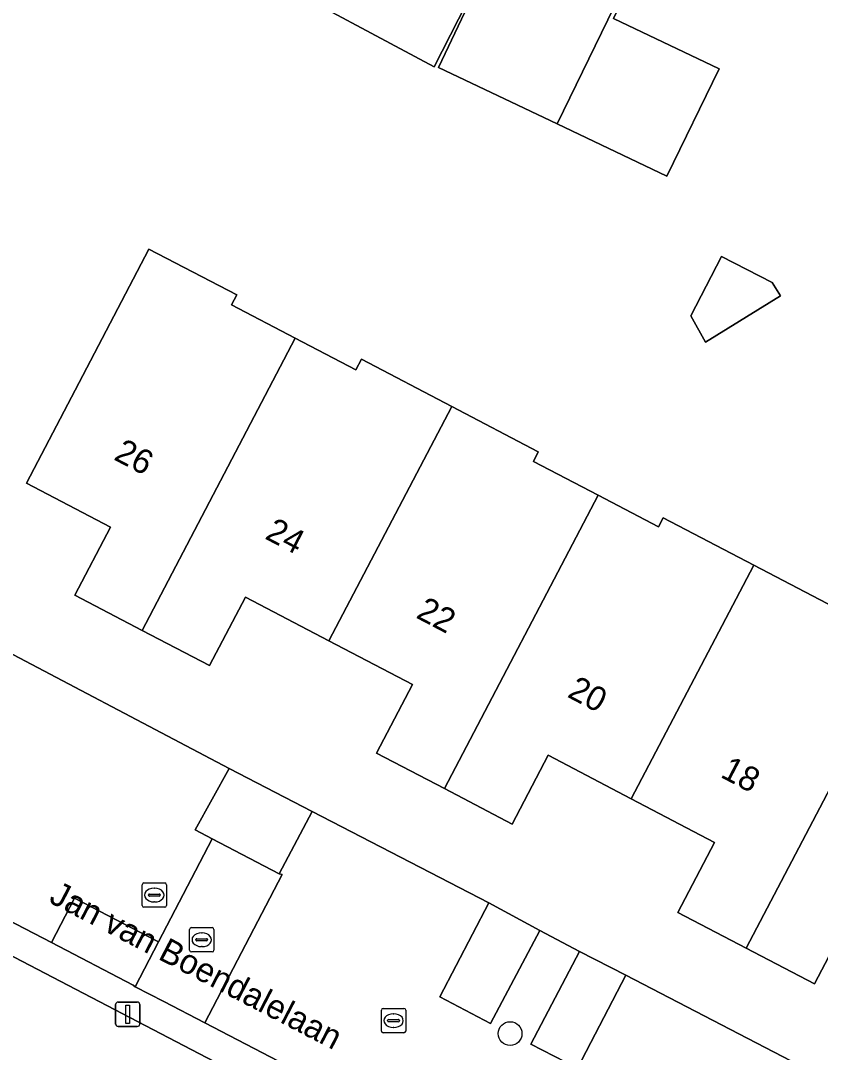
# Model space of a CAD drawing. Extents: x 160349 to 161355, y 381727 to 382854.
# Drawn here: x 160733.31 to 160766.17, y 382411.9 to 382454.27 of the extents above; entities that cross this region are included whole.
import ezdxf

# ---------------------------------------------------------------- set-up
doc = ezdxf.new("R2010")
doc.units = 0
for name, color, linetype in [('IMGEO_Boom', 7, 'Continuous'), ('IMGEO_Erf', 7, 'Continuous'), ('IMGEO_Groenvoorziening', 7, 'Continuous'), ('IMGEO_Kolk', 7, 'Continuous'), ('IMGEO_Lichtmast', 7, 'Continuous'), ('IMGEO_Openbare_ruimte_label', 7, 'Continuous'), ('IMGEO_Pand', 7, 'Continuous'), ('IMGEO_Pand_nummerreeks', 7, 'Continuous'), ('IMGEO_Parkeervlak_open', 7, 'Continuous'), ('IMGEO_Rioolput', 7, 'Continuous'), ('IMGEO_Voetpad_open', 7, 'Continuous'), ('IMGEO_Woonerf_open', 7, 'Continuous')]:
    doc.layers.add(name, color=color, linetype=linetype)

msp = doc.modelspace()

# ---------------------------------------------------------------- linework, layer by layer
at = {"layer": 'IMGEO_Boom'}
msp.add_circle((160753.42, 382412.667), 0.489, dxfattribs=at)
at = {"layer": 'IMGEO_Erf'}
for points in [[(160753.641, 382458.935), (160750.295, 382452.378), (160743.332, 382456.11)], [(160767.405, 382417.538), (160765.925, 382414.706), (160763.12, 382416.172), (160760.315, 382417.638), (160761.822, 382420.523), (160758.4, 382422.312), (160754.98, 382424.099), (160753.503, 382421.274), (160750.719, 382422.729), (160747.937, 382424.183), (160749.414, 382427.009), (160745.979, 382428.804), (160742.547, 382430.598), (160741.075, 382427.781), (160738.305, 382429.229), (160735.537, 382430.675), (160736.999, 382433.471), (160733.557, 382435.27), (160735.873, 382439.702), (160738.583, 382444.889), (160742.192, 382443.003), (160741.976, 382442.591), (160744.597, 382441.222), (160747.082, 382439.923), (160747.311, 382440.361), (160751.024, 382438.42), (160754.58, 382436.561), (160754.376, 382436.17), (160757.04, 382434.777), (160759.514, 382433.484), (160759.706, 382433.851), (160763.432, 382431.904), (160767.042, 382430.017)], [(160698.651, 382444.432), (160706.474, 382440.908), (160712.236, 382438.345), (160715.645, 382436.842), (160717.302, 382436.075), (160719.442, 382435.153), (160727.083, 382431.251), (160727.158, 382431.213), (160731.438, 382429.052), (160731.474, 382429.033), (160741.875, 382423.552), (160745.289, 382421.796), (160752.547, 382418.032), (160754.638, 382416.907), (160756.272, 382416.046), (160758.175, 382415.068), (160765.328, 382411.355)], [(160782.234, 382390.225), (160773.298, 382394.819), (160708.642, 382428.527)]]:
    msp.add_lwpolyline(points, dxfattribs=at)
for points in [[(160750.475, 382452.351), (160753.04, 382457.734), (160757.962, 382455.388), (160758.122, 382455.312), (160757.669, 382454.362), (160762.014, 382452.291), (160759.861, 382447.879), (160755.348, 382450.029)], [(160762.111, 382444.577), (160764.189, 382443.508), (160764.527, 382442.962), (160761.449, 382441.065), (160760.839, 382442.143)]]:
    msp.add_lwpolyline(points, close=True, dxfattribs=at)
at = {"layer": 'IMGEO_Groenvoorziening'}
msp.add_lwpolyline([(160743.928, 382419.236), (160745.289, 382421.796), (160741.875, 382423.552), (160740.483, 382421.031), (160741.176, 382420.67)], close=True, dxfattribs=at)
at = {"layer": 'IMGEO_Kolk'}
for p, q in [((160738.305, 382417.93), (160738.305, 382418.782)), ((160738.38, 382418.856), (160739.232, 382418.856)), ((160738.793, 382418.636), (160738.818, 382418.636)), ((160739.306, 382418.782), (160739.306, 382417.93)), ((160738.564, 382418.35), (160738.564, 382418.362)), ((160739.002, 382418.313), (160738.604, 382418.313)), ((160738.607, 382418.399), (160739.005, 382418.399)), ((160739.048, 382418.362), (160739.048, 382418.35)), ((160739.232, 382417.856), (160738.38, 382417.856)), ((160738.816, 382418.076), (160738.791, 382418.076)), ((160748.131, 382412.775), (160748.131, 382413.627)), ((160748.206, 382413.701), (160749.058, 382413.701)), ((160748.619, 382413.481), (160748.644, 382413.481)), ((160749.132, 382413.627), (160749.132, 382412.775)), ((160748.39, 382413.195), (160748.39, 382413.207)), ((160748.828, 382413.158), (160748.43, 382413.158)), ((160748.433, 382413.244), (160748.831, 382413.244)), ((160748.874, 382413.207), (160748.874, 382413.195)), ((160749.058, 382412.701), (160748.206, 382412.701)), ((160748.642, 382412.921), (160748.617, 382412.921))]:
    msp.add_line(p, q, dxfattribs=at)
for points in [[(160738.305, 382417.93), (160738.305, 382418.782)], [(160738.38, 382418.856), (160739.232, 382418.856)], [(160739.306, 382418.782), (160739.306, 382417.93)], [(160739.232, 382417.856), (160738.38, 382417.856)], [(160748.131, 382412.775), (160748.131, 382413.627)], [(160748.206, 382413.701), (160749.058, 382413.701)], [(160749.132, 382413.627), (160749.132, 382412.775)], [(160749.058, 382412.701), (160748.206, 382412.701)]]:
    msp.add_lwpolyline(points, dxfattribs=at)
for centre, radius, start, end in [((160738.382, 382418.78), 0.0765, 91.552, 178.448), ((160738.382, 382418.78), 0.0765, 91.552, 178.448), ((160739.23, 382418.78), 0.0765, 1.552, 88.448), ((160739.23, 382418.78), 0.0765, 1.552, 88.448), ((160738.604, 382418.359), 0.0403, 85.8775, 175.7526), ((160738.601, 382418.349), 0.0366, 178.938, 274.7102), ((160739.005, 382418.356), 0.043, 264.8664, 352.4533), ((160739.009, 382418.361), 0.0386, 1.7309, 96.639), ((160738.382, 382417.932), 0.0765, 181.552, 268.448), ((160738.382, 382417.932), 0.0765, 181.552, 268.448), ((160739.23, 382417.932), 0.0765, 271.552, 358.448), ((160739.23, 382417.932), 0.0765, 271.552, 358.448), ((160748.208, 382413.625), 0.0765, 91.552, 178.448), ((160748.208, 382413.625), 0.0765, 91.552, 178.448), ((160749.056, 382413.625), 0.0765, 1.552, 88.448), ((160749.056, 382413.625), 0.0765, 1.552, 88.448), ((160748.43, 382413.204), 0.0403, 85.8775, 175.7526), ((160748.427, 382413.194), 0.0366, 178.938, 274.7102), ((160748.831, 382413.201), 0.043, 264.8664, 352.4533), ((160748.835, 382413.206), 0.0386, 1.7309, 96.639), ((160748.208, 382412.777), 0.0765, 181.552, 268.448), ((160748.208, 382412.777), 0.0765, 181.552, 268.448), ((160749.056, 382412.777), 0.0765, 271.552, 358.448), ((160749.056, 382412.777), 0.0765, 271.552, 358.448)]:
    msp.add_arc(centre, radius, start, end, dxfattribs=at)
for centre, major_axis, ratio, start_param, end_param in [((160738.792, 382418.356), (-0.387, 0.002), 0.722429, 4.712389, 7.853982), ((160738.817, 382418.356), (-0.39, 0.002), 0.717154, 1.570796, 4.712389), ((160748.618, 382413.201), (-0.387, 0.002), 0.722429, 4.712389, 7.853982), ((160748.643, 382413.201), (-0.39, 0.002), 0.717154, 1.570796, 4.712389)]:
    msp.add_ellipse(centre, major_axis=major_axis, ratio=ratio, start_param=start_param, end_param=end_param, dxfattribs=at)
at = {"layer": 'IMGEO_Lichtmast'}
for p, q in [((160737.216, 382413.062), (160737.216, 382413.862)), ((160737.216, 382413.862), (160737.216, 382413.062)), ((160737.316, 382413.962), (160738.106, 382413.962)), ((160738.106, 382413.962), (160737.316, 382413.962)), ((160738.206, 382413.862), (160738.206, 382413.062)), ((160738.206, 382413.062), (160738.206, 382413.862)), ((160738.106, 382412.962), (160737.316, 382412.962)), ((160737.316, 382412.962), (160738.106, 382412.962))]:
    msp.add_line(p, q, dxfattribs=at)
msp.add_lwpolyline([(160737.636, 382413.837), (160737.786, 382413.837), (160737.786, 382413.087), (160737.636, 382413.087), (160737.636, 382413.837)], dxfattribs=at)
for centre, start, end in [((160737.316, 382413.862), 90, 180), ((160737.316, 382413.862), 90, 180), ((160738.106, 382413.862), 0, 90), ((160738.106, 382413.862), 360, 90), ((160737.316, 382413.062), 180, 270), ((160737.316, 382413.062), 180, 270), ((160738.106, 382413.062), 270, 0), ((160738.106, 382413.062), 270, 0)]:
    msp.add_arc(centre, 0.1, start, end, dxfattribs=at)
at = {"layer": 'IMGEO_Pand'}
for points in [[(160759.775, 382470.935), (160760.825, 382472.981), (160767.276, 382486.202), (160762.739, 382488.416), (160760.547, 382483.923), (160759.252, 382481.27), (160760.845, 382480.439), (160756.903, 382472.336), (160755.732, 382469.929), (160751.695, 382471.893), (160743.332, 382456.11), (160750.295, 382452.378), (160753.641, 382458.935), (160750.945, 382460.379), (160753.023, 382464.255), (160755.64, 382462.853)], [(160757.962, 382455.388), (160753.04, 382457.734), (160750.475, 382452.351), (160755.348, 382450.029)], [(160757.962, 382455.388), (160755.348, 382450.029), (160759.861, 382447.879), (160762.014, 382452.291), (160757.669, 382454.362), (160758.122, 382455.312)], [(160738.305, 382429.229), (160744.597, 382441.222), (160741.976, 382442.591), (160742.192, 382443.003), (160738.583, 382444.889), (160735.873, 382439.702), (160733.557, 382435.27), (160736.999, 382433.471), (160735.537, 382430.675)], [(160762.111, 382444.577), (160760.839, 382442.143), (160761.449, 382441.065), (160764.527, 382442.962), (160764.189, 382443.508)], [(160745.979, 382428.804), (160751.024, 382438.42), (160747.311, 382440.361), (160747.082, 382439.923), (160744.597, 382441.222), (160738.305, 382429.229), (160741.075, 382427.781), (160742.547, 382430.598)], [(160757.04, 382434.777), (160754.376, 382436.17), (160754.58, 382436.561), (160751.024, 382438.42), (160745.979, 382428.804), (160749.414, 382427.009), (160747.937, 382424.183), (160750.719, 382422.729)], [(160757.04, 382434.777), (160750.719, 382422.729), (160753.503, 382421.274), (160754.98, 382424.099), (160758.4, 382422.312), (160763.432, 382431.904), (160759.706, 382433.851), (160759.514, 382433.484)], [(160758.4, 382422.312), (160761.822, 382420.523), (160760.315, 382417.638), (160763.12, 382416.172), (160769.471, 382428.276), (160766.848, 382429.647), (160767.042, 382430.017), (160763.432, 382431.904)], [(160770.77, 382415.779), (160775.846, 382425.453), (160772.108, 382427.407), (160771.899, 382427.007), (160769.471, 382428.276), (160763.12, 382416.172), (160765.925, 382414.706), (160767.405, 382417.538)]]:
    msp.add_lwpolyline(points, close=True, dxfattribs=at)
at = {"layer": 'IMGEO_Parkeervlak_open'}
for points in [[(160734.587, 382416.413), (160737.936, 382414.651), (160738.024, 382414.59), (160738.981, 382416.436), (160735.527, 382418.224)], [(160754.638, 382416.907), (160752.547, 382418.032), (160750.53, 382414.18), (160752.613, 382413.084)], [(160758.175, 382415.068), (160756.272, 382416.046), (160754.279, 382412.238), (160756.194, 382411.243)]]:
    msp.add_lwpolyline(points, close=True, dxfattribs=at)
at = {"layer": 'IMGEO_Rioolput'}
for p, q in [((160740.253, 382416.095), (160740.253, 382416.947)), ((160740.328, 382417.021), (160741.18, 382417.021)), ((160741.254, 382416.947), (160741.254, 382416.095)), ((160740.512, 382416.515), (160740.512, 382416.527)), ((160740.95, 382416.478), (160740.552, 382416.478)), ((160740.555, 382416.564), (160740.953, 382416.564)), ((160740.741, 382416.801), (160740.766, 382416.801)), ((160740.996, 382416.527), (160740.996, 382416.515)), ((160741.18, 382416.021), (160740.328, 382416.021)), ((160740.764, 382416.241), (160740.739, 382416.241))]:
    msp.add_line(p, q, dxfattribs=at)
for points in [[(160740.253, 382416.095), (160740.253, 382416.947)], [(160740.328, 382417.021), (160741.18, 382417.021)], [(160741.254, 382416.947), (160741.254, 382416.095)], [(160741.18, 382416.021), (160740.328, 382416.021)]]:
    msp.add_lwpolyline(points, dxfattribs=at)
for centre, radius, start, end in [((160740.33, 382416.945), 0.0765, 91.552, 178.448), ((160740.33, 382416.945), 0.0765, 91.552, 178.448), ((160741.178, 382416.945), 0.0765, 1.552, 88.448), ((160741.178, 382416.945), 0.0765, 1.552, 88.448), ((160740.552, 382416.524), 0.0403, 85.8775, 175.7526), ((160740.549, 382416.514), 0.0366, 178.938, 274.7102), ((160740.953, 382416.521), 0.043, 264.8664, 352.4533), ((160740.957, 382416.526), 0.0386, 1.7309, 96.639), ((160740.33, 382416.097), 0.0765, 181.552, 268.448), ((160740.33, 382416.097), 0.0765, 181.552, 268.448), ((160741.178, 382416.097), 0.0765, 271.552, 358.448), ((160741.178, 382416.097), 0.0765, 271.552, 358.448)]:
    msp.add_arc(centre, radius, start, end, dxfattribs=at)
for centre, major_axis, ratio, start_param, end_param in [((160740.74, 382416.521), (-0.387, 0.002), 0.722429, 4.712389, 7.853982), ((160740.765, 382416.521), (-0.39, 0.002), 0.717154, 1.570796, 4.712389)]:
    msp.add_ellipse(centre, major_axis=major_axis, ratio=ratio, start_param=start_param, end_param=end_param, dxfattribs=at)
at = {"layer": 'IMGEO_Voetpad_open'}
for points in [[(160689.692, 382438.362), (160708.642, 382428.527), (160773.298, 382394.819), (160782.234, 382390.225), (160786.93, 382387.809)], [(160789.244, 382390.463), (160784.094, 382393.118), (160783.112, 382391.22), (160779.203, 382393.223), (160779.942, 382394.678), (160777.147, 382396.08), (160774.595, 382397.343), (160773.85, 382395.861), (160771.593, 382397.084), (160765.508, 382400.26), (160759.042, 382403.665), (160740.882, 382413.11), (160739.195, 382413.984), (160738.024, 382414.59), (160737.936, 382414.651), (160734.587, 382416.413), (160729.127, 382419.233), (160725.287, 382421.216), (160725.157, 382421.283), (160725.087, 382421.319), (160720.833, 382423.582), (160720.791, 382423.604), (160708.959, 382429.716), (160692.572, 382438.247)]]:
    msp.add_lwpolyline(points, dxfattribs=at)
at = {"layer": 'IMGEO_Woonerf_open'}
for points in [[(160729.127, 382419.233), (160734.587, 382416.413), (160735.527, 382418.224), (160738.981, 382416.436), (160741.176, 382420.67), (160740.483, 382421.031), (160741.875, 382423.552), (160731.474, 382429.033)], [(160765.328, 382411.355), (160758.175, 382415.068), (160756.194, 382411.243), (160754.279, 382412.238), (160756.272, 382416.046), (160754.638, 382416.907), (160752.613, 382413.084), (160750.53, 382414.18), (160752.547, 382418.032), (160745.289, 382421.796), (160743.928, 382419.236), (160744.054, 382419.2), (160740.882, 382413.11), (160759.042, 382403.665)]]:
    msp.add_lwpolyline(points, dxfattribs=at)
msp.add_lwpolyline([(160744.054, 382419.2), (160743.928, 382419.236), (160741.176, 382420.67), (160738.981, 382416.436), (160738.024, 382414.59), (160739.195, 382413.984), (160740.882, 382413.11)], close=True, dxfattribs=at)

# ---------------------------------------------------------------- texts
at = {"layer": 'IMGEO_Openbare_ruimte_label'}
msp.add_text('Jan van Boendalelaan', height=1, rotation=332.5642, dxfattribs=at).set_placement((160734.429, 382418.081))
at = {"layer": 'IMGEO_Pand_nummerreeks'}
for s, p in [('26', (160737.098, 382436.261)), ('24', (160743.308, 382433.013)), ('22', (160749.514, 382429.766)), ('20', (160755.73, 382426.514)), ('18', (160762.019, 382423.224))]:
    msp.add_text(s, height=1, rotation=332.3828, dxfattribs=at).set_placement(p)

doc.saveas('drawing.dxf')
